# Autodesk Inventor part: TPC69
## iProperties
Shininess: 64.0
Length Units: 11272
Angle Units: 11279
Time Units: 11290
Mass Units: 11286
Length Display Precision: 3
Angle Display Precision: 2
Compacted: True
Part Number: TPC69
Document SubType Name: Modeling
Created: 2004-08
Designer: Lori
Manufacturer: Standard
Standards Organization: Custom
Density: 0.0
Volumn: 0.0
Area: 0.0
PropertySet Name: Model Information
Control State: 0
Master: False
Checked Out: False
Author: Lori
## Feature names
1. Base1
